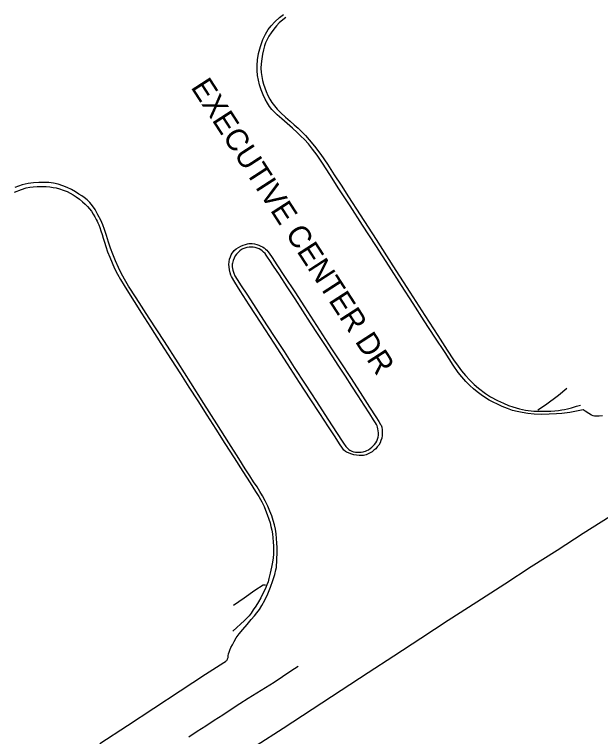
# Model space of a CAD drawing. Extents: x 1961683 to 1977751, y 798292 to 805767.
# Drawn here: x 1963306.2 to 1963450.9, y 800308.9 to 800487 of the extents above; entities that cross this region are included whole.
import ezdxf

# ---------------------------------------------------------------- set-up
doc = ezdxf.new("R2010")
doc.units = 0
for name, color, linetype in [('RD_EX_Conc', 7, 'Continuous'), ('RD_EX_Road', 7, 'Continuous'), ('RD_EX_Road_Paint', 7, 'Continuous'), ('RD_TX_RoadID', 7, 'Continuous')]:
    doc.layers.add(name, color=color, linetype=linetype)

msp = doc.modelspace()

# ---------------------------------------------------------------- linework, layer by layer
at = {"layer": 'RD_EX_Conc'}
msp.add_lwpolyline([(1963392.69, 800378.31), (1963392.37, 800378.26), (1963391.88, 800378.23), (1963391.27, 800378.24), (1963390.62, 800378.31), (1963389.94, 800378.45), (1963389.26, 800378.66), (1963388.64, 800378.89), (1963388.14, 800379.12), (1963387.93, 800379.25), (1963387.73, 800379.39), (1963387.55, 800379.57), (1963387.17, 800380.05), (1963386.46, 800381.12), (1963385.33, 800382.86), (1963383.72, 800385.37), (1963381.62, 800388.62), (1963379.24, 800392.27), (1963376.6, 800396.31), (1963373.6, 800400.91), (1963370.31, 800405.99), (1963367.11, 800410.92), (1963364.15, 800415.45), (1963361.96, 800418.85), (1963360.58, 800421.04), (1963359.8, 800422.38), (1963359.62, 800422.75), (1963359.43, 800423.35), (1963359.27, 800424.04), (1963359.17, 800424.76), (1963359.15, 800425.41), (1963359.2, 800426.03), (1963359.32, 800426.66), (1963359.5, 800427.25), (1963359.7, 800427.74), (1963359.95, 800428.18), (1963360.27, 800428.61), (1963360.47, 800428.81), (1963360.96, 800429.2), (1963361.55, 800429.56), (1963362.12, 800429.87), (1963362.66, 800430.13), (1963363.2, 800430.34), (1963363.74, 800430.5), (1963364.02, 800430.54), (1963364.31, 800430.56), (1963364.91, 800430.53), (1963365.49, 800430.44), (1963366.03, 800430.31), (1963366.55, 800430.14), (1963367.03, 800429.93), (1963367.47, 800429.7), (1963367.86, 800429.45), (1963368.2, 800429.18), (1963368.5, 800428.89), (1963368.77, 800428.59), (1963369.07, 800428.17), (1963369.79, 800427.13), (1963371.01, 800425.31), (1963372.9, 800422.42), (1963375.39, 800418.6), (1963377.8, 800414.91), (1963380.05, 800411.47), (1963382.27, 800408.05), (1963384.5, 800404.61), (1963386.79, 800401.09), (1963389.13, 800397.5), (1963391.53, 800393.82), (1963393.85, 800390.21), (1963395.41, 800387.8), (1963396.16, 800386.65), (1963396.59, 800385.95), (1963396.71, 800385.72), (1963396.79, 800385.52), (1963396.86, 800385.26), (1963396.94, 800384.6), (1963396.96, 800383.88), (1963396.93, 800383.2), (1963396.85, 800382.56), (1963396.68, 800381.94), (1963396.44, 800381.35), (1963396.12, 800380.84), (1963395.75, 800380.37), (1963395.37, 800379.94), (1963394.95, 800379.56), (1963394.5, 800379.21), (1963394.01, 800378.91), (1963393.48, 800378.64), (1963393, 800378.43)], close=True, dxfattribs=at)
at = {"layer": 'RD_EX_Road'}
for points in [[(1963446.58, 800389.54), (1963443.3, 800388.89), (1963441.98, 800388.68), (1963441.31, 800388.65), (1963439.97, 800388.54), (1963438.23, 800388.42), (1963436.33, 800388.37), (1963434.49, 800388.42), (1963432.92, 800388.6), (1963431.56, 800388.84), (1963430.33, 800389.08), (1963429.14, 800389.4), (1963427.87, 800389.84), (1963426.61, 800390.36), (1963425.43, 800390.9), (1963424.35, 800391.43), (1963423.39, 800391.93), (1963422.45, 800392.48), (1963421.42, 800393.2), (1963420.41, 800393.99), (1963419.49, 800394.74), (1963418.59, 800395.57), (1963417.61, 800396.55), (1963416.64, 800397.63), (1963415.75, 800398.76), (1963414.51, 800400.56), (1963412.49, 800403.63), (1963410, 800407.45), (1963407.37, 800411.48), (1963404.61, 800415.74), (1963401.73, 800420.22), (1963398.67, 800424.97), (1963395.41, 800430.03), (1963392.13, 800435.09), (1963389.05, 800439.83), (1963386.3, 800444.05), (1963384.02, 800447.57), (1963382.22, 800450.33), (1963380.89, 800452.31), (1963379.81, 800453.8), (1963378.77, 800455.1), (1963377.8, 800456.19), (1963376.92, 800457.06), (1963375.98, 800457.92), (1963374.82, 800458.99), (1963373.54, 800460.15), (1963372.22, 800461.3), (1963371.08, 800462.3), (1963370.33, 800463.01), (1963369.76, 800463.62), (1963369.2, 800464.32), (1963368.65, 800465.16), (1963368.13, 800466.14), (1963367.63, 800467.26), (1963367.13, 800468.48), (1963366.7, 800469.7), (1963366.41, 800470.85), (1963366.22, 800471.99), (1963366.11, 800473.19), (1963366.1, 800474.48), (1963366.19, 800475.89), (1963366.45, 800477.44), (1963366.91, 800479.18), (1963367.51, 800480.84), (1963368.17, 800482.19), (1963368.87, 800483.3), (1963369.58, 800484.27), (1963370.46, 800485.21), (1963371.66, 800486.28), (1963372.65, 800487.05)], [(1963373.2, 800486.31), (1963372.48, 800485.75), (1963371.56, 800484.95), (1963370.85, 800484.21), (1963370.2, 800483.41), (1963369.58, 800482.54), (1963369.03, 800481.68), (1963368.57, 800480.84), (1963368.2, 800480.05), (1963367.93, 800479.28), (1963367.67, 800478.35), (1963367.43, 800477.26), (1963367.23, 800476.1), (1963367.09, 800474.9), (1963367.05, 800473.78), (1963367.13, 800472.76), (1963367.27, 800471.75), (1963367.47, 800470.75), (1963367.7, 800469.82), (1963367.97, 800468.95), (1963368.33, 800468.04), (1963368.77, 800467.07), (1963369.25, 800466.16), (1963369.77, 800465.31), (1963370.36, 800464.5), (1963371.04, 800463.71), (1963371.97, 800462.77), (1963373.13, 800461.69), (1963374.23, 800460.71), (1963375.25, 800459.85), (1963376.2, 800459), (1963377.1, 800458.14), (1963378.01, 800457.2), (1963378.98, 800456.12), (1963380.25, 800454.55), (1963381.81, 800452.48), (1963383.46, 800450.11), (1963385.15, 800447.52), (1963386.84, 800444.9), (1963388.66, 800442.06), (1963391.53, 800437.59), (1963395.46, 800431.5), (1963399.62, 800425.05), (1963403.8, 800418.59), (1963407.54, 800412.81), (1963410.7, 800407.89), (1963413.05, 800404.26), (1963414.6, 800401.9), (1963415.72, 800400.26), (1963416.55, 800399.14), (1963417.5, 800398.02), (1963418.59, 800396.83), (1963419.65, 800395.8), (1963420.74, 800394.88), (1963422.5, 800393.56), (1963423.67, 800392.71), (1963425.42, 800391.84), (1963426.93, 800391.14), (1963428.18, 800390.61), (1963429.19, 800390.25), (1963430.06, 800390), (1963430.87, 800389.78), (1963431.63, 800389.61), (1963432.34, 800389.47), (1963433.03, 800389.36), (1963433.72, 800389.28), (1963434.42, 800389.22), (1963435.12, 800389.18), (1963435.87, 800389.16), (1963436.7, 800389.17), (1963437.61, 800389.19), (1963438.61, 800389.24), (1963439.59, 800389.31), (1963440.48, 800389.4), (1963441.28, 800389.5), (1963441.98, 800389.62), (1963442.74, 800389.79), (1963443.72, 800390.05), (1963444.92, 800390.4), (1963445.89, 800390.71)], [(1963327.26, 800307.24), (1963334.15, 800311.7), (1963340.62, 800315.92), (1963347.14, 800320.2), (1963353.38, 800324.33), (1963356.98, 800326.67), (1963357.9, 800327.22), (1963358.31, 800327.49), (1963358.47, 800327.61), (1963358.6, 800327.74), (1963358.7, 800327.87), (1963358.78, 800328), (1963358.83, 800328.14), (1963358.92, 800328.47), (1963359, 800328.87), (1963359.08, 800329.31), (1963359.17, 800329.75), (1963359.33, 800330.25), (1963359.61, 800330.87), (1963359.99, 800331.58), (1963360.41, 800332.37), (1963360.94, 800333.26), (1963361.66, 800334.26), (1963362.56, 800335.38), (1963363.62, 800336.62), (1963364.64, 800337.78), (1963365.42, 800338.69), (1963366.07, 800339.47), (1963366.66, 800340.26), (1963367.28, 800341.23), (1963368.01, 800342.57), (1963368.76, 800344.13), (1963369.44, 800345.8), (1963370.02, 800347.45), (1963370.46, 800348.95), (1963370.76, 800350.08), (1963370.88, 800350.65), (1963370.92, 800351.15), (1963370.96, 800352.08), (1963370.99, 800353.1), (1963371.02, 800353.88), (1963371.03, 800354.64), (1963371.03, 800355.58), (1963370.99, 800356.65), (1963370.91, 800357.81), (1963370.79, 800358.98), (1963370.61, 800360.06), (1963370.38, 800361.13), (1963370.07, 800362.25), (1963369.7, 800363.39), (1963369.28, 800364.54), (1963368.77, 800365.75), (1963368.12, 800367.06), (1963367.43, 800368.33), (1963366.78, 800369.42), (1963366.08, 800370.51), (1963365.25, 800371.78), (1963364.28, 800373.27), (1963363.19, 800375.01), (1963361.59, 800377.54), (1963359.14, 800381.4), (1963356.15, 800386.07), (1963352.99, 800391.05), (1963349.76, 800396.15), (1963346.58, 800401.15), (1963343.23, 800406.38), (1963339.49, 800412.15), (1963336.26, 800417.16), (1963334.4, 800420.06), (1963333.36, 800421.78), (1963332.56, 800423.22), (1963331.87, 800424.63), (1963331.17, 800426.24), (1963330.5, 800427.89), (1963329.93, 800429.41), (1963329.41, 800430.91), (1963328.9, 800432.51), (1963328.43, 800434), (1963328, 800435.19), (1963327.51, 800436.32), (1963326.83, 800437.65), (1963326.1, 800438.91), (1963325.46, 800439.87), (1963324.82, 800440.63), (1963324.12, 800441.31), (1963323.42, 800441.89), (1963322.8, 800442.33), (1963322.11, 800442.75), (1963321.24, 800443.29), (1963320.25, 800443.85), (1963319.24, 800444.34), (1963318.17, 800444.78), (1963317.02, 800445.16), (1963315.85, 800445.44), (1963314.71, 800445.59), (1963313.53, 800445.63), (1963312.26, 800445.63), (1963310.94, 800445.55), (1963309.62, 800445.36), (1963308.14, 800444.99), (1963306.33, 800444.35)], [(1963306.2, 800443.23), (1963307.98, 800443.89), (1963309.12, 800444.26), (1963309.97, 800444.44), (1963310.85, 800444.55), (1963311.82, 800444.61), (1963312.93, 800444.61), (1963314.02, 800444.57), (1963314.94, 800444.49), (1963315.74, 800444.39), (1963316.5, 800444.25), (1963317.32, 800444.04), (1963318.27, 800443.72), (1963319.2, 800443.34), (1963319.97, 800442.98), (1963320.69, 800442.56), (1963321.47, 800442.04), (1963322.26, 800441.46), (1963322.99, 800440.87), (1963323.66, 800440.28), (1963324.23, 800439.71), (1963324.74, 800439.12), (1963325.2, 800438.49), (1963325.62, 800437.82), (1963326.04, 800437.12), (1963326.39, 800436.49), (1963326.62, 800436.06), (1963326.81, 800435.66), (1963327.04, 800435.15), (1963327.3, 800434.5), (1963327.56, 800433.68), (1963327.83, 800432.78), (1963328.09, 800431.89), (1963328.4, 800430.92), (1963328.77, 800429.79), (1963329.2, 800428.52), (1963329.72, 800427.16), (1963330.3, 800425.76), (1963330.93, 800424.38), (1963331.62, 800423.02), (1963332.37, 800421.68), (1963333.26, 800420.22), (1963334.35, 800418.45), (1963335.75, 800416.22), (1963337.59, 800413.35), (1963339.81, 800409.9), (1963342.37, 800405.92), (1963344.93, 800401.94), (1963347.16, 800398.44), (1963349.26, 800395.14), (1963351.45, 800391.71), (1963353.67, 800388.23), (1963355.88, 800384.77), (1963358.11, 800381.26), (1963360.4, 800377.68), (1963362.55, 800374.32), (1963364.37, 800371.51), (1963365.72, 800369.39), (1963366.5, 800368.13), (1963366.94, 800367.38), (1963367.26, 800366.84), (1963367.55, 800366.33), (1963367.86, 800365.67), (1963368.21, 800364.82), (1963368.62, 800363.72), (1963369.01, 800362.59), (1963369.3, 800361.64), (1963369.52, 800360.78), (1963369.72, 800359.87), (1963369.88, 800358.94), (1963370, 800357.98), (1963370.08, 800356.98), (1963370.13, 800355.92), (1963370.15, 800354.88), (1963370.12, 800353.95), (1963370.03, 800353), (1963369.88, 800351.94), (1963369.66, 800350.7), (1963369.35, 800349.24), (1963369.03, 800347.91), (1963368.8, 800347.07), (1963368.52, 800346.33), (1963368.06, 800345.31), (1963367.53, 800344.21), (1963367.02, 800343.19), (1963366.47, 800342.19), (1963365.82, 800341.14), (1963365.16, 800340.17), (1963364.62, 800339.39), (1963364.13, 800338.76), (1963363.66, 800338.2), (1963363.03, 800337.56), (1963360.15, 800334.93)], [(1963435.36, 800389.51), (1963437.29, 800390.73), (1963440.47, 800393.11), (1963442.58, 800394.84)], [(1963451.36, 800388.07), (1963450.56, 800387.94), (1963449.78, 800387.93), (1963449.4, 800387.97), (1963449.03, 800388.06), (1963448.67, 800388.2), (1963447.95, 800388.6), (1963447.08, 800389.18), (1963446.58, 800389.54)], [(1963365.89, 800306.73), (1963372.53, 800311.05), (1963379.72, 800315.72), (1963386.89, 800320.4), (1963393.48, 800324.71), (1963399.89, 800328.89), (1963406.49, 800333.2), (1963413.3, 800337.63), (1963420.3, 800342.18), (1963427.21, 800346.65), (1963433.75, 800350.85), (1963440.14, 800354.93), (1963446.62, 800359.07), (1963453.22, 800363.29)], [(1963368.15, 800346.27), (1963367.57, 800346.31), (1963365.52, 800344.93), (1963362.9, 800343.08), (1963360.29, 800341.3)]]:
    msp.add_lwpolyline(points, dxfattribs=at)
msp.add_lwpolyline([(1963390.06, 800379.15), (1963390.38, 800379.1), (1963390.84, 800379.07), (1963391.35, 800379.05), (1963391.8, 800379.07), (1963392.16, 800379.13), (1963392.3, 800379.16), (1963392.52, 800379.24), (1963392.82, 800379.35), (1963393.22, 800379.49), (1963393.63, 800379.7), (1963394.04, 800379.98), (1963394.42, 800380.28), (1963394.77, 800380.61), (1963395.09, 800380.97), (1963395.39, 800381.36), (1963395.63, 800381.79), (1963395.82, 800382.26), (1963395.96, 800382.76), (1963396.04, 800383.29), (1963396.06, 800383.82), (1963396.02, 800384.35), (1963395.94, 800384.82), (1963395.83, 800385.22), (1963395.71, 800385.57), (1963395.58, 800385.9), (1963395.32, 800386.36), (1963394.86, 800387.07), (1963393.93, 800388.51), (1963392.52, 800390.66), (1963391.01, 800392.98), (1963389.47, 800395.39), (1963387.89, 800397.84), (1963386.28, 800400.33), (1963384.65, 800402.84), (1963382.98, 800405.39), (1963381.2, 800408.11), (1963379.31, 800411), (1963377.41, 800413.94), (1963375.48, 800416.89), (1963373.53, 800419.88), (1963371.62, 800422.79), (1963370.19, 800424.97), (1963369.28, 800426.36), (1963368.7, 800427.22), (1963368.37, 800427.66), (1963368.06, 800428.05), (1963367.72, 800428.42), (1963367.38, 800428.74), (1963367.02, 800428.99), (1963366.59, 800429.22), (1963366.09, 800429.43), (1963365.59, 800429.58), (1963365.1, 800429.65), (1963364.61, 800429.67), (1963364.11, 800429.64), (1963363.58, 800429.55), (1963363.05, 800429.4), (1963362.62, 800429.23), (1963362.28, 800429.04), (1963361.87, 800428.74), (1963361.4, 800428.33), (1963361.01, 800427.91), (1963360.72, 800427.49), (1963360.44, 800426.97), (1963360.18, 800426.35), (1963360.01, 800425.73), (1963359.96, 800425.43), (1963359.94, 800425.12), (1963359.96, 800424.78), (1963360.09, 800424.01), (1963360.33, 800423.25), (1963360.63, 800422.59), (1963361.19, 800421.68), (1963362.19, 800420.14), (1963363.55, 800418.07), (1963365.19, 800415.54), (1963366.94, 800412.83), (1963368.62, 800410.23), (1963370.49, 800407.37), (1963372.75, 800403.9), (1963375.29, 800400), (1963377.98, 800395.86), (1963380.75, 800391.58), (1963383.54, 800387.26), (1963385.83, 800383.72), (1963387.09, 800381.8), (1963387.44, 800381.28), (1963388.02, 800380.48), (1963388.48, 800379.98), (1963388.72, 800379.78), (1963388.97, 800379.6), (1963389.51, 800379.34), (1963389.92, 800379.19)], close=True, dxfattribs=at)
at = {"layer": 'RD_EX_Road_Paint'}
msp.add_lwpolyline([(1963349.24, 800308.87), (1963351.33, 800310.25), (1963353.41, 800311.63), (1963355.52, 800312.97), (1963357.63, 800314.31), (1963359.72, 800315.69), (1963361.81, 800317.06), (1963363.92, 800318.4), (1963366.03, 800319.73), (1963368.16, 800321.04), (1963370.29, 800322.35), (1963372.36, 800323.76), (1963374.43, 800325.16), (1963376.26, 800326.33)], dxfattribs=at)

# ---------------------------------------------------------------- texts
at = {"layer": 'RD_TX_RoadID'}
msp.add_text('EXECUTIVE CENTER DR', height=5.4, rotation=302.8927, dxfattribs=at).set_placement((1963349.61, 800469.09))

doc.saveas('drawing.dxf')
